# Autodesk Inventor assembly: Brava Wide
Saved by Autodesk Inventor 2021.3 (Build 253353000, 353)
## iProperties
Created: 2022-09
Part Number: Brava Wide
Document SubType Name: Assembly
Designer: Administrator
Title: Brava Wide v7
Author: Administrator
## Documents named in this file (3)
- c:\worker\convert-fusion-r05\tmp\job-1\75\output\files\ad3db4e7-0b7c-4940-84af-d749230bf43f\ca4601fb-f531-4d83-8fe3-fb9d7b7e657d.iam
- c:\worker\convert-fusion-r05\tmp\job-1\75\output\files\ad3db4e7-0b7c-4940-84af-d749230bf43f\Brava Wide.ipt
- c:\worker\convert-fusion-r05\tmp\job-1\75\output\files\ad3db4e7-0b7c-4940-84af-d749230bf43f\Part4.ipt
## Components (2 placed, 2 different names)
1. Brava Wide:1
2. Part4
